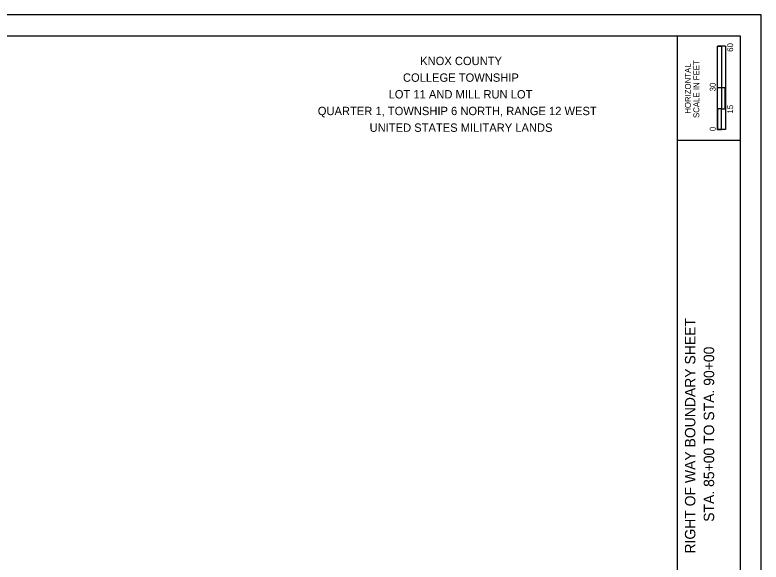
# Model space of a CAD drawing. Extents: x -2 to 1376856, y -4 to 32.
# Drawn here: x 16.11 to 34, y 8.88 to 22 of the extents above; entities that cross this region are included whole.
import ezdxf

# ---------------------------------------------------------------- set-up
doc = ezdxf.new("R2010")
doc.units = 0
for name, color, linetype in [('SH_Border', 7, 'Continuous'), ('SH_Cut_Line', 7, 'Continuous'), ('SH_Data', 7, 'Continuous'), ('SH_Text', 7, 'Continuous')]:
    doc.layers.add(name, color=color, linetype=linetype)

msp = doc.modelspace()

# ---------------------------------------------------------------- linework, layer by layer
at = {"layer": 'SH_Border'}
for p, q in [((32, 0.5), (32, 21.5)), ((32, 19), (33.5, 19))]:
    msp.add_line(p, q, dxfattribs=at)
msp.add_lwpolyline([(1.5, 21.5), (33.5, 21.5), (33.5, 0.5), (1.5, 0.5)], close=True, dxfattribs=at)
at = {"layer": 'SH_Cut_Line'}
msp.add_lwpolyline([(0, 0), (34, 0), (34, 22), (0, 22)], close=True, dxfattribs=at)
at = {"layer": 'SH_Data'}
for p, q in [((32.957, 19.25), (32.957, 21.25)), ((33.144, 21.25), (32.957, 21.25)), ((32.957, 20.25), (32.957, 21.25)), ((32.957, 21.25), (33.05, 21.25)), ((33.05, 21.25), (33.051, 21.25)), ((33.051, 21.25), (33.051, 20.25)), ((33.144, 21.25), (33.144, 19.25)), ((33.051, 20.25), (32.957, 20.25)), ((33.143, 20.25), (33.05, 20.25)), ((33.05, 20.25), (33.05, 19.75)), ((33.143, 19.75), (33.143, 20.25)), ((33.05, 19.75), (32.957, 19.75)), ((32.957, 19.75), (32.957, 19.25)), ((33.05, 19.25), (33.05, 19.75)), ((33.05, 19.75), (33.143, 19.75)), ((33.144, 19.25), (32.957, 19.25)), ((32.957, 19.25), (33.05, 19.25))]:
    msp.add_line(p, q, dxfattribs=at)

# ---------------------------------------------------------------- texts
for s, height, p in [('60', 0.14, (33.33, 21.116)), ('HORIZONTAL', 0.14, (32.315, 19.63)), ('SCALE IN FEET', 0.14, (32.517, 19.529)), ('30', 0.14, (32.91, 20.166)), ('15', 0.14, (33.33, 19.636)), ('0', 0.14, (32.91, 19.214)), ('RIGHT OF WAY BOUNDARY SHEET', 0.25, (32.425, 9.085)), ('STA. 85+00 TO STA. 90+00', 0.25, (32.875, 9.847))]:
    msp.add_text(s, height=height, rotation=90, dxfattribs=at).set_placement(p)
at = {"layer": 'SH_Text'}
for s, p in [('KNOX COUNTY', (25.828, 20.797)), ('COLLEGE TOWNSHIP', (25.415, 20.397)), ('LOT 11 AND MILL RUN LOT', (25.071, 19.997)), ('QUARTER 1, TOWNSHIP 6 NORTH, RANGE 12 WEST', (23.374, 19.597)), ('UNITED STATES MILITARY LANDS', (24.616, 19.197))]:
    msp.add_text(s, height=0.2, dxfattribs=at).set_placement(p)

doc.saveas('drawing.dxf')
